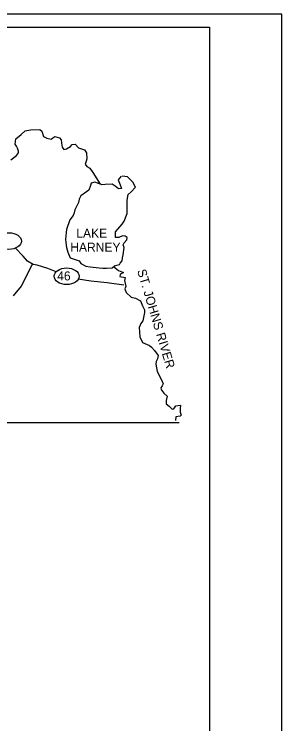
# Model space of a CAD drawing. Extents: x 2157516 to 2331756, y 2153820 to 2265756.
# Drawn here: x 2310288 to 2331756, y 2208739 to 2265756 of the extents above; entities that cross this region are included whole.
import ezdxf

# ---------------------------------------------------------------- set-up
doc = ezdxf.new("R2010")
doc.units = 0
for name, color, linetype in [('ActivePointCell_dp', 7, 'Continuous'), ('Default', 7, 'Continuous'), ('PlotBorder_dp', 7, 'Continuous'), ('RefPtLine', 7, 'Continuous'), ('SheetBorder_dp', 7, 'Continuous')]:
    doc.layers.add(name, color=color, linetype=linetype)

msp = doc.modelspace()

# ---------------------------------------------------------------- linework, layer by layer
at = {"layer": 'ActivePointCell_dp'}
msp.add_line((2325948, 2264700), (2325948, 2264700), dxfattribs=at)
at = {"layer": 'Default'}
for p, q in [((2310833, 2256086), (2311168, 2256387)), ((2311168, 2256387), (2311603, 2256454)), ((2311603, 2256454), (2312339, 2256488)), ((2312339, 2256488), (2312506, 2256354)), ((2312506, 2256354), (2312640, 2255918)), ((2310364, 2255316), (2310431, 2255751)), ((2310431, 2255751), (2310833, 2256086)), ((2312640, 2255918), (2312908, 2255785)), ((2312908, 2255785), (2313243, 2255718)), ((2313243, 2255718), (2313377, 2255818)), ((2313377, 2255818), (2313544, 2255918)), ((2313544, 2255918), (2313912, 2255818)), ((2313912, 2255818), (2314046, 2255651)), ((2314046, 2255651), (2314080, 2255383)), ((2310465, 2255149), (2310364, 2255316)), ((2310565, 2254981), (2310465, 2255149)), ((2314080, 2255383), (2314146, 2255082)), ((2314146, 2255082), (2314280, 2254881)), ((2314481, 2254948), (2314816, 2255115)), ((2314816, 2255115), (2314950, 2255282)), ((2314950, 2255282), (2315184, 2255316)), ((2315184, 2255316), (2315452, 2255015)), ((2310465, 2254412), (2310632, 2254613)), ((2310632, 2254747), (2310565, 2254981)), ((2310632, 2254613), (2310632, 2254747)), ((2314280, 2254881), (2314481, 2254948)), ((2315452, 2255015), (2315920, 2254847)), ((2315920, 2254847), (2316088, 2254613)), ((2316088, 2254613), (2316121, 2254144)), ((2310030, 2254044), (2310465, 2254412)), ((2316054, 2253944), (2315987, 2253709)), ((2316121, 2254144), (2316054, 2253944)), ((2315987, 2253709), (2316121, 2253508)), ((2316121, 2253508), (2316356, 2253375)), ((2316356, 2253375), (2316590, 2253040)), ((2316590, 2253040), (2317174, 2252106)), ((2316474, 2252177), (2316404, 2252003)), ((2316751, 2252246), (2316474, 2252177)), ((2317063, 2252142), (2316751, 2252246)), ((2317029, 2252177), (2316890, 2252212)), ((2317306, 2252038), (2317029, 2252177)), ((2318868, 2252732), (2318625, 2252455)), ((2318625, 2252455), (2318798, 2252038)), ((2319388, 2252698), (2318937, 2252732)), ((2319804, 2252246), (2319388, 2252698)), ((2320012, 2251865), (2319804, 2252246)), ((2316265, 2251622), (2316092, 2251483)), ((2316404, 2252003), (2316265, 2251622)), ((2317584, 2252073), (2317306, 2252038)), ((2318139, 2252108), (2317584, 2252073)), ((2318382, 2251934), (2318139, 2252108)), ((2318659, 2251726), (2318382, 2251934)), ((2318902, 2251761), (2318659, 2251726)), ((2318798, 2252038), (2318902, 2251761)), ((2319666, 2251483), (2320012, 2251865)), ((2315641, 2251171), (2315502, 2250893)), ((2316092, 2251483), (2315641, 2251171)), ((2319353, 2250824), (2319423, 2251275)), ((2319423, 2251275), (2319666, 2251483)), ((2315433, 2250615), (2315155, 2250026)), ((2315502, 2250893), (2315433, 2250615)), ((2319353, 2250268), (2319353, 2250824)), ((2315155, 2250026), (2315086, 2249783)), ((2319353, 2249748), (2319353, 2250268)), ((2315016, 2249574), (2314739, 2249227)), ((2315086, 2249783), (2315016, 2249574)), ((2319110, 2249123), (2319353, 2249748)), ((2314739, 2249227), (2314496, 2248464)), ((2318417, 2248256), (2318937, 2248880)), ((2318937, 2248880), (2319110, 2249123)), ((2314461, 2248221), (2314392, 2247666)), ((2314496, 2248464), (2314461, 2248221)), ((2318417, 2247805), (2318417, 2248256)), ((2314392, 2247666), (2314427, 2247423)), ((2318694, 2247805), (2318417, 2247805)), ((2318972, 2247943), (2318694, 2247805)), ((2319180, 2247909), (2318972, 2247943)), ((2319110, 2247388), (2319319, 2247631)), ((2319353, 2247805), (2319180, 2247909)), ((2319319, 2247631), (2319353, 2247805)), ((2314427, 2247423), (2314496, 2247006)), ((2319041, 2247215), (2319110, 2247388)), ((2319110, 2247006), (2319041, 2247215)), ((2311005, 2246312), (2310393, 2246965)), ((2314496, 2247006), (2314600, 2246625)), ((2314600, 2246625), (2314774, 2246174)), ((2319041, 2246417), (2319110, 2247006)), ((2311364, 2245908), (2311005, 2246312)), ((2311812, 2245639), (2311364, 2245908)), ((2314774, 2246174), (2315502, 2245931)), ((2315502, 2245931), (2315641, 2245723)), ((2318798, 2245757), (2318937, 2245931)), ((2318937, 2245931), (2318972, 2246174)), ((2318972, 2246174), (2319041, 2246417)), ((2311731, 2245651), (2310855, 2243899)), ((2312126, 2245594), (2311812, 2245639)), ((2312979, 2245325), (2312126, 2245594)), ((2313646, 2245054), (2312979, 2245325)), ((2315641, 2245723), (2316023, 2245514)), ((2316023, 2245514), (2316369, 2245445)), ((2316369, 2245445), (2317098, 2245375)), ((2317098, 2245375), (2317410, 2245341)), ((2317410, 2245341), (2317688, 2245341)), ((2317688, 2245341), (2318139, 2245375)), ((2318139, 2245375), (2318347, 2245549)), ((2318261, 2245477), (2318665, 2245174)), ((2318347, 2245549), (2318729, 2245653)), ((2318665, 2245174), (2319067, 2245006)), ((2318799, 2244839), (2318765, 2244671)), ((2318866, 2244906), (2318799, 2244839)), ((2319067, 2245006), (2318866, 2244906)), ((2316433, 2244293), (2315430, 2244453)), ((2317734, 2244158), (2316433, 2244293)), ((2318765, 2244671), (2319203, 2244587)), ((2319203, 2244587), (2319136, 2244353)), ((2319136, 2244353), (2319236, 2243884)), ((2310855, 2243899), (2310204, 2243139)), ((2319080, 2243979), (2317734, 2244158)), ((2319236, 2243884), (2319170, 2243683)), ((2319170, 2243683), (2319270, 2243382)), ((2319270, 2243382), (2319672, 2243014)), ((2319672, 2243014), (2320006, 2242947)), ((2320006, 2242947), (2320408, 2242712)), ((2320408, 2242712), (2320575, 2242311)), ((2320575, 2242311), (2320743, 2242009)), ((2320743, 2242009), (2320743, 2241775)), ((2320676, 2241507), (2320609, 2241106)), ((2320743, 2241775), (2320676, 2241507)), ((2320441, 2240905), (2320308, 2240570)), ((2320609, 2241106), (2320441, 2240905)), ((2320308, 2240570), (2320374, 2239834)), ((2320374, 2239834), (2320575, 2239365)), ((2320575, 2239365), (2321144, 2239131)), ((2321144, 2239131), (2321312, 2238997)), ((2321312, 2238997), (2321546, 2238729)), ((2321546, 2238729), (2321847, 2238327)), ((2321780, 2238060), (2321680, 2237859)), ((2321847, 2238327), (2321780, 2238060)), ((2321680, 2237859), (2321646, 2237624)), ((2321646, 2237624), (2321747, 2237055)), ((2321747, 2237055), (2322115, 2236386)), ((2322115, 2236386), (2322249, 2236051)), ((2322148, 2235884), (2322015, 2235683)), ((2322249, 2236051), (2322148, 2235884)), ((2322048, 2235616), (2322282, 2235315)), ((2322282, 2235315), (2322552, 2235056)), ((2322552, 2235056), (2322485, 2234721)), ((2322485, 2234721), (2322485, 2234453)), ((2322485, 2234453), (2322720, 2234252)), ((2322720, 2234252), (2322954, 2234018)), ((2322954, 2234018), (2323088, 2234052)), ((2323088, 2234052), (2323255, 2234286)), ((2323255, 2234286), (2323623, 2234353)), ((2323623, 2234353), (2323590, 2234085)), ((2323590, 2234085), (2323590, 2233784)), ((2323255, 2233416), (2323222, 2233114)), ((2323590, 2233449), (2323255, 2233416)), ((2323590, 2233784), (2323690, 2233549)), ((2323690, 2233549), (2323590, 2233449)), ((2290968, 2232944), (2323515, 2232944))]:
    msp.add_line(p, q, dxfattribs=at)
for centre in [(2309856, 2247530), (2314496, 2244698)]:
    msp.add_ellipse(centre, major_axis=(1004, 0), ratio=0.66697, dxfattribs=at)
at = {"layer": 'PlotBorder_dp'}
msp.add_lwpolyline([(2157516, 2153820), (2331756, 2153820), (2331756, 2265756), (2157516, 2265756)], close=True, dxfattribs=at)
at = {"layer": 'RefPtLine'}
msp.add_line((2318729, 2245653), (2318798, 2245757), dxfattribs=at)
at = {"layer": 'SheetBorder_dp'}
for p, q in [((2163324, 2264700), (2325948, 2264700)), ((2325948, 2264700), (2325948, 2154876))]:
    msp.add_line(p, q, dxfattribs=at)

# ---------------------------------------------------------------- texts
at = {"layer": 'Default'}
for s, height, rotation, p in [('LAKE', 723.6, 0, (2315270, 2247796)), ('HARNEY', 723.6, 0, (2314784, 2246673)), ('46', 723.6, 0, (2313737, 2244366)), ('ST. JOHNS RIVER', 723.65, 286.6354, (2320141, 2245150))]:
    msp.add_text(s, height=height, rotation=rotation, dxfattribs=at).set_placement(p)

doc.saveas('drawing.dxf')
